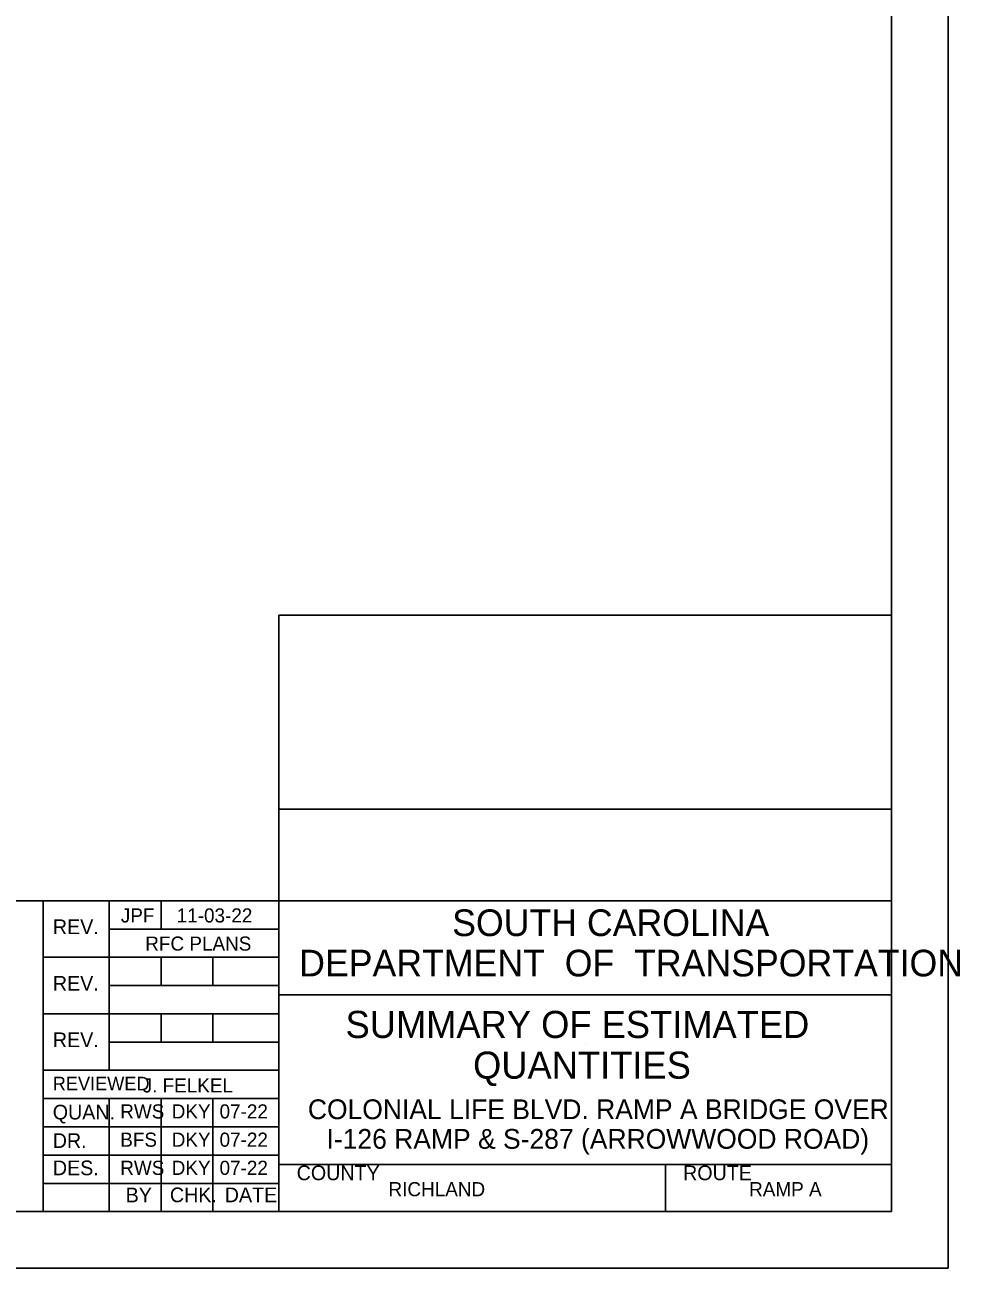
# Model space of a CAD drawing. Extents: x -125.5 to -89.4, y -5.1 to 16.9.
# Drawn here: x -97.7 to -89.43, y -5.07 to 5.93 of the extents above; entities that cross this region are included whole.
import ezdxf

# ---------------------------------------------------------------- set-up
doc = ezdxf.new("R2010")
doc.units = 0
for name, color, linetype in [('BR_BORDER LINES', 7, 'Continuous'), ('BR_TEXT', 7, 'Continuous'), ('Level 31', 7, 'Continuous')]:
    doc.layers.add(name, color=color, linetype=linetype)

msp = doc.modelspace()

# ---------------------------------------------------------------- linework, layer by layer
at = {"layer": 'BR_BORDER LINES'}
for p, q in [((-90.033, -4.566), (-90.033, 16.434)), ((-95.45, -4.566), (-95.45, 0.71)), ((-95.45, 0.71), (-90.033, 0.71)), ((-95.45, -1.004), (-90.033, -1.004)), ((-102.899, -1.816), (-97.534, -1.816)), ((-97.534, -4.566), (-97.534, -1.816)), ((-97.534, -1.816), (-90.033, -1.816)), ((-96.95, -1.816), (-96.95, -3.316)), ((-96.492, -2.066), (-96.492, -1.816)), ((-96.95, -2.066), (-95.45, -2.066)), ((-97.534, -2.316), (-95.45, -2.316)), ((-96.492, -2.566), (-96.492, -2.316)), ((-96.034, -2.566), (-96.034, -2.316)), ((-96.95, -2.566), (-95.45, -2.566)), ((-95.45, -2.649), (-95.45, -2.649)), ((-95.45, -2.649), (-90.033, -2.649)), ((-97.534, -2.816), (-95.45, -2.816)), ((-96.492, -3.066), (-96.492, -2.816)), ((-96.034, -3.066), (-96.034, -2.816)), ((-96.95, -3.066), (-95.45, -3.066)), ((-97.534, -3.316), (-95.45, -3.316)), ((-97.534, -3.566), (-95.45, -3.566)), ((-96.95, -3.566), (-96.95, -4.566)), ((-96.492, -3.566), (-96.492, -4.566)), ((-96.034, -3.566), (-96.034, -4.566)), ((-97.534, -3.816), (-95.45, -3.816)), ((-97.534, -4.066), (-95.45, -4.066)), ((-95.45, -4.149), (-90.033, -4.149)), ((-95.353, -4.149), (-90.033, -4.149)), ((-92.033, -4.566), (-92.033, -4.149)), ((-97.534, -4.316), (-95.45, -4.316)), ((-123.699, -4.566), (-90.033, -4.566))]:
    msp.add_line(p, q, dxfattribs=at)
at = {"layer": 'Level 31'}
msp.add_line((-92.742, -3.09), (-92.742, -3.09), dxfattribs=at)
msp.add_lwpolyline([(-125.533, 16.934), (-125.533, -5.066), (-89.533, -5.066), (-89.533, 16.934)], dxfattribs=at)

# ---------------------------------------------------------------- texts
at = {"layer": 'BR_TEXT'}
for s, height, p in [('JPF', 0.125, (-96.848, -2.008)), ('11-03-22', 0.125, (-96.354, -2.008)), ('SOUTH CAROLINA', 0.23587, (-93.918, -2.128)), ('REV.', 0.13, (-97.449, -2.111)), ('RFC PLANS', 0.125, (-96.632, -2.257)), ('DEPARTMENT  OF  TRANSPORTATION', 0.23587, (-95.271, -2.485)), ('REV.', 0.13, (-97.449, -2.611)), ('SUMMARY OF ESTIMATED ', 0.24, (-94.861, -3.03)), ('REV.', 0.13, (-97.449, -3.111)), ('QUANTITIES', 0.24, (-93.733, -3.39)), ('REVIEWED', 0.12, (-97.45, -3.493)), ('J. FELKEL', 0.125, (-96.655, -3.512)), ('QUAN.', 0.13, (-97.45, -3.751)), ('RWS', 0.125, (-96.853, -3.742)), ('DKY', 0.125, (-96.398, -3.742)), ('07-22', 0.125, (-95.975, -3.742)), ('COLONIAL LIFE BLVD. RAMP A BRIDGE OVER', 0.175, (-95.194, -3.748)), ('I-126 RAMP & S-287 (ARROWWOOD ROAD)', 0.175, (-95.029, -4.01)), ('DR.', 0.13, (-97.45, -4.003)), ('BFS', 0.125, (-96.853, -3.992)), ('DKY', 0.125, (-96.398, -3.992)), ('07-22', 0.125, (-95.975, -3.992)), ('DES.', 0.13, (-97.449, -4.244)), ('RWS', 0.125, (-96.853, -4.241)), ('DKY', 0.125, (-96.398, -4.241)), ('07-22', 0.125, (-95.975, -4.241)), ('COUNTY', 0.13, (-95.293, -4.288)), ('ROUTE', 0.13, (-91.876, -4.288)), ('BY', 0.13, (-96.805, -4.484)), ('CHK.', 0.13, (-96.414, -4.483)), ('DATE', 0.13, (-95.929, -4.483)), ('RICHLAND', 0.125, (-94.481, -4.43)), ('RAMP A', 0.125, (-91.292, -4.43))]:
    msp.add_text(s, height=height, dxfattribs=at).set_placement(p)

doc.saveas('drawing.dxf')
